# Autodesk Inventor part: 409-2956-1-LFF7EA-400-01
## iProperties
Created: 2010-06
Part Number: 409-2956-1-LFF7EA-400-01
Material: 1/16"Thk PLASTIC
Document SubType Name: Modeling
Designer: S. Boerckel
Engineer: Steve Boerckel
Mass: 230.369 g
Surface Area: 3121.56 cm^2
Volume: 245.074 cm^3
Density: 0.94 g/cm^3
Description: TAG
SMR: =<Material>
Length: 20.000 in
Wide: 12.000 in
Thickness: 0.063 in
Author: S. Boerckel
Revision Number: 0
Subject: DEMIN WATER FORWARDING PUMP SKID-7EA
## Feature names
1. Extrusion1
2. Hole1
